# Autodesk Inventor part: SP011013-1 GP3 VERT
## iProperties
Created: 2013-01
Part Number: SP011013-1 GP3 VERT
Material: PVC-U
Document SubType Name: Modeling
Designer: Administrator
Density: 1.4 g/cm^3
Mass: 305.215 g
Surface Area: 1940.71 cm^2
Volume: 218.011 cm^3
Author: Administrator
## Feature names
1. Extrusion1
